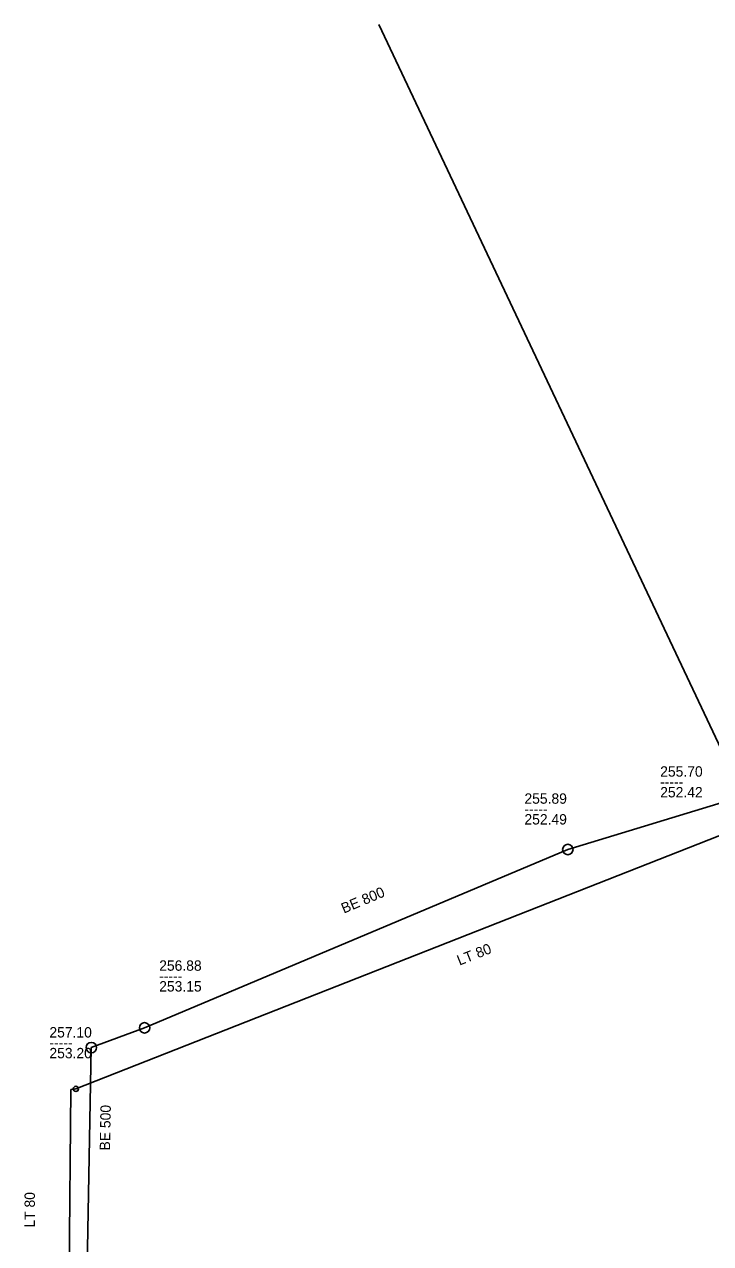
# Model space of a CAD drawing. Extents: x -647357 to -646700, y -1072205 to -1071664.
# Drawn here: x -647268.8 to -647202.6, y -1071781.5 to -1071664.1 of the extents above; entities that cross this region are included whole.
import ezdxf

# ---------------------------------------------------------------- set-up
doc = ezdxf.new("R2010")
doc.units = 0
for name, color, linetype in [('Level 20', 7, 'Continuous'), ('Level 24', 7, 'Continuous'), ('Level 26', 7, 'Continuous'), ('Level 40', 7, 'Continuous'), ('Level 41', 7, 'Continuous'), ('Level 44', 7, 'Continuous')]:
    doc.layers.add(name, color=color, linetype=linetype)

msp = doc.modelspace()

# ---------------------------------------------------------------- linework, layer by layer
at = {"layer": 'Level 20'}
for p, q in [((-647198.35, -1071740.88), (-647234.6, -1071664.09)), ((-647198.35, -1071740.88), (-647263.8, -1071766.64)), ((-647264.49, -1071792.27), (-647264.3, -1071766.69)), ((-647264.3, -1071766.69), (-647263.8, -1071766.64))]:
    msp.add_line(p, q, dxfattribs=at)
at = {"layer": 'Level 26'}
msp.add_circle((-647263.8, -1071766.64), 0.25, dxfattribs=at)
at = {"layer": 'Level 40'}
for p, q in [((-647216.4, -1071743.58), (-647200.46, -1071738.72)), ((-647257.18, -1071760.76), (-647216.4, -1071743.58)), ((-647262.31, -1071762.66), (-647257.18, -1071760.76)), ((-647262.71, -1071783.78), (-647262.31, -1071762.66))]:
    msp.add_line(p, q, dxfattribs=at)
at = {"layer": 'Level 41'}
for centre in [(-647216.4, -1071743.58), (-647257.18, -1071760.76), (-647262.31, -1071762.66)]:
    msp.add_circle(centre, 0.5, dxfattribs=at)

# ---------------------------------------------------------------- texts
at = {"layer": 'Level 24'}
for rotation, p in [(21.484, (-647226.84, -1071754.77)), (89.889, (-647267.75, -1071780))]:
    msp.add_text('LT 80', height=1, rotation=rotation, dxfattribs=at).set_placement(p)
at = {"layer": 'Level 44'}
for s, p in [('255.70', (-647207.5, -1071736.56)), ('-----', (-647207.5, -1071737.56)), ('252.42', (-647207.5, -1071738.56)), ('255.89', (-647220.58, -1071739.17)), ('-----', (-647220.58, -1071740.17)), ('252.49', (-647220.58, -1071741.17)), ('256.88', (-647255.77, -1071755.26)), ('-----', (-647255.77, -1071756.26)), ('253.15', (-647255.77, -1071757.26)), ('257.10', (-647266.35, -1071761.69)), ('-----', (-647266.35, -1071762.69)), ('253.20', (-647266.35, -1071763.69))]:
    msp.add_text(s, height=1, dxfattribs=at).set_placement(p)
for s, rotation, p in [('BE 800', 22.845, (-647237.98, -1071749.76)), ('BE 500', 88.915, (-647260.51, -1071772.58))]:
    msp.add_text(s, height=1, rotation=rotation, dxfattribs=at).set_placement(p)

doc.saveas('drawing.dxf')
